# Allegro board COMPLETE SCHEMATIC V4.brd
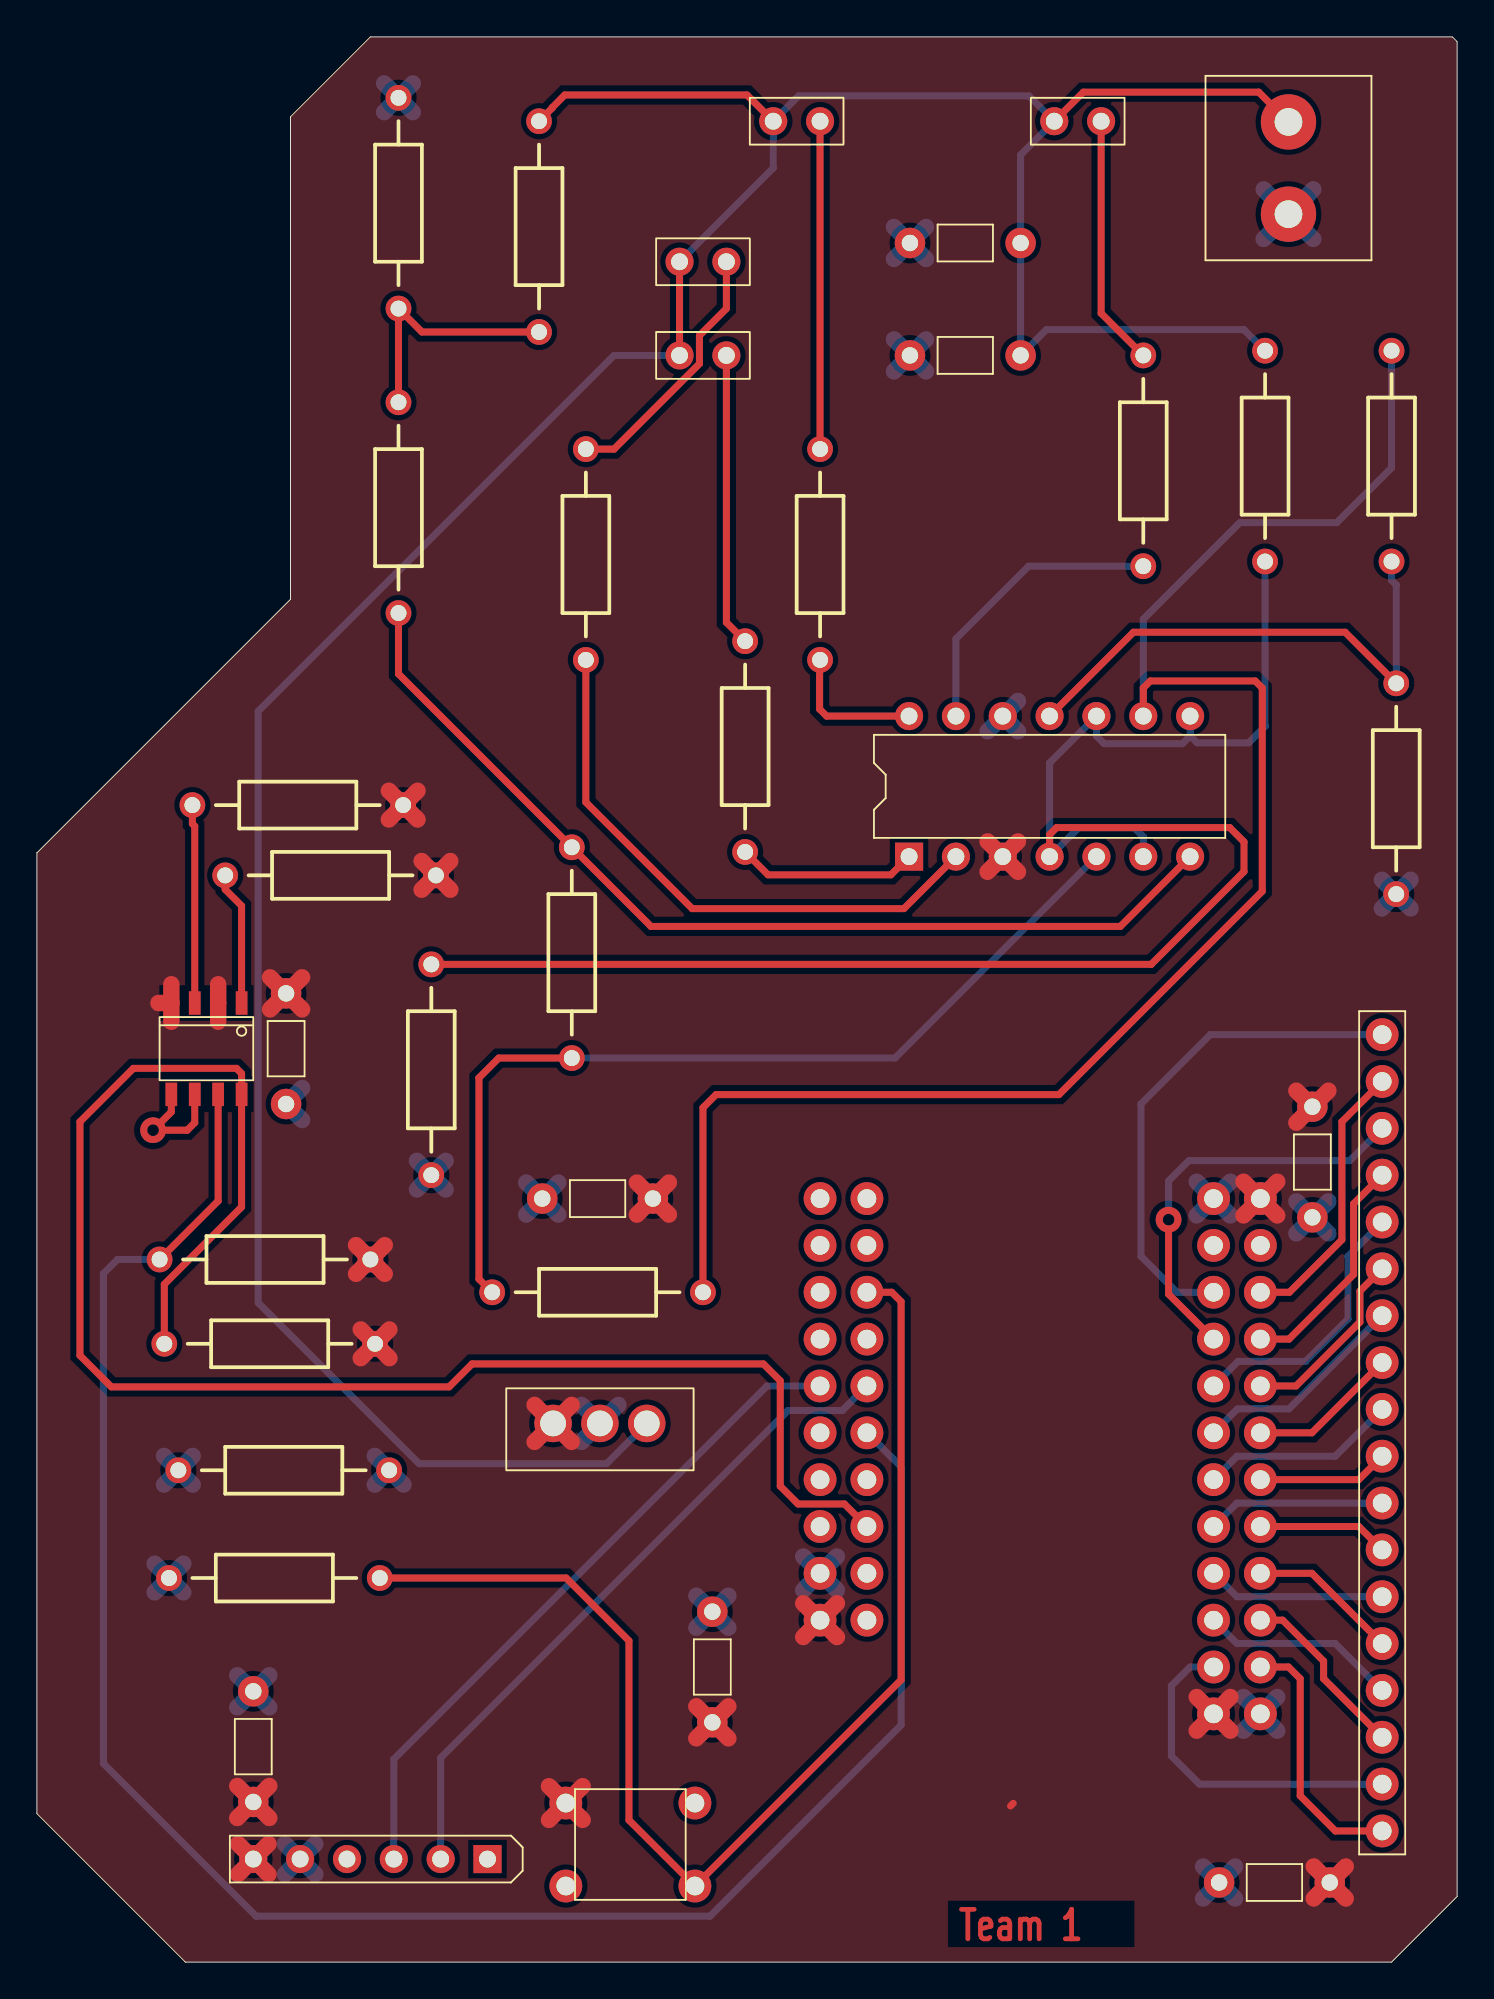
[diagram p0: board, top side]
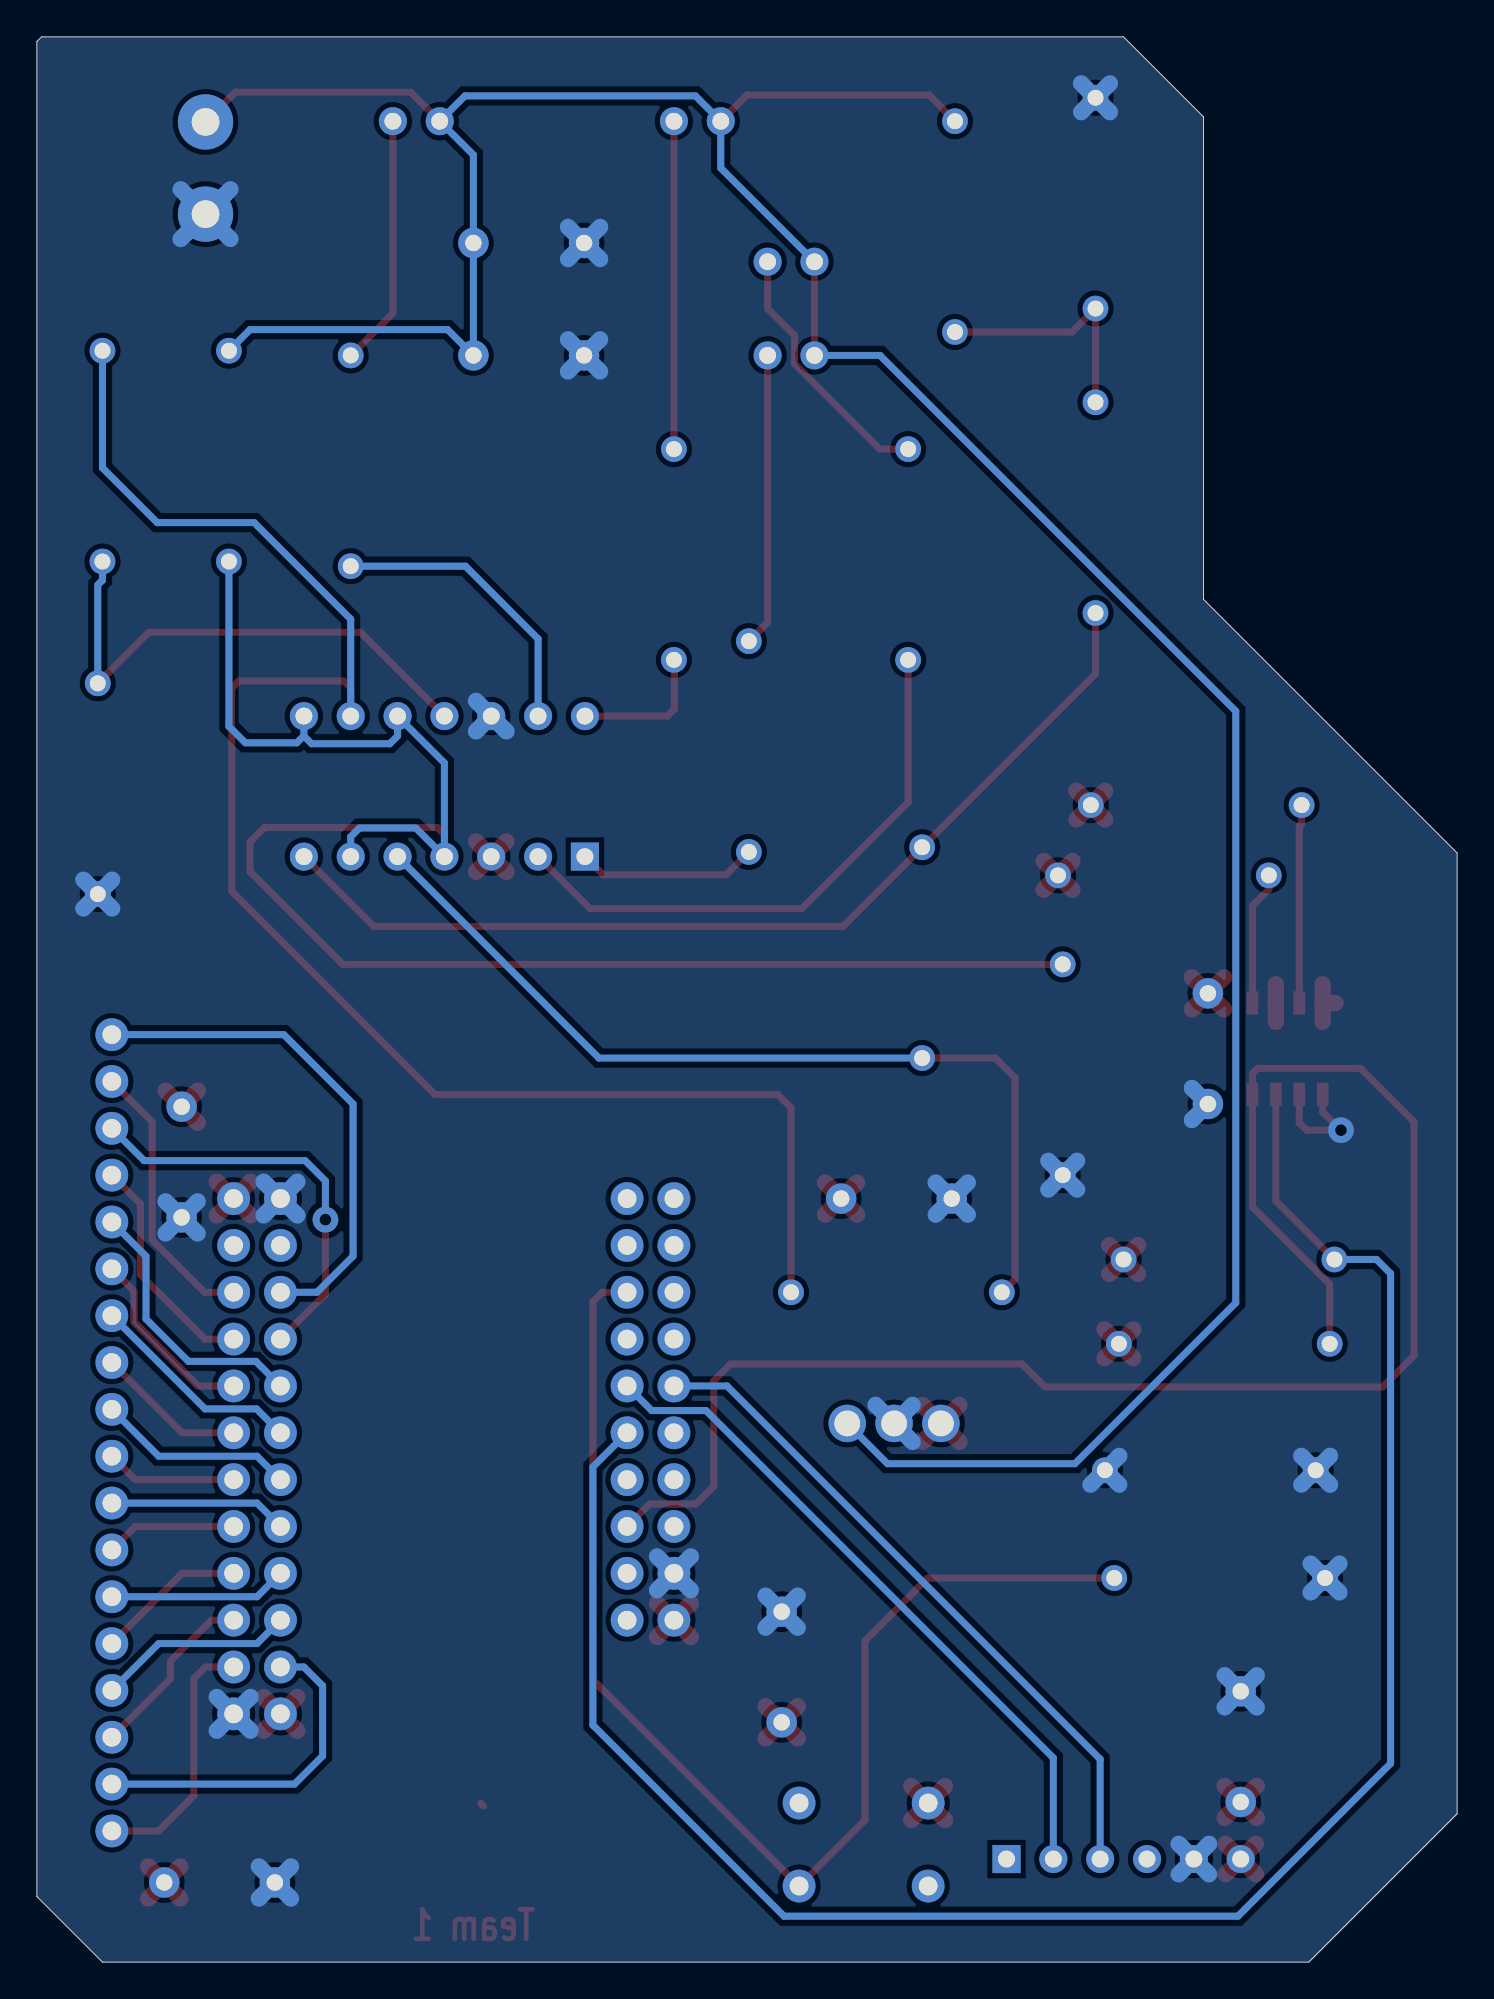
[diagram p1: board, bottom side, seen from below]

Outline 77.01 x 104.39 mm; copper layers: TOP, BOTTOM. Coordinates in mm from the lower left corner of the outline.
Outline path: 0,60.15 0,8.05 8.05,0 73.46,0 77.01,3.56 77.01,104.14 76.76,104.39 18.08,104.39 13.75,100.06 13.75,73.9 0,60.15

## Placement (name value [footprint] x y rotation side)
BT1  BATTERY  [2POS5MMCON]  67.87 97.28 0 top
C1  0.33uF 50V  [CAP1]  50.34 87.12 180 top
C2  0.1uF 50V  [CAP1]  30.4 41.4 180 top
C3  0.1uF 50V  [CAP1]  50.34 93.22 180 top
C4  0.1uF 50V  [CAP1]  36.63 16 90 top
C5  0.1 uF 50V  [CAP1]  69.16 43.38 270 top
C6  0.1uF 50V  [CAP1]  67.11 4.32 180 top
C7  0.1uF 50V  [CAP1]  11.73 11.68 270 top
C8  CAP NP  [CAP1]  13.51 49.53 270 top
D1  BLU  [JUMPER2]  34.85 87.12 0 top
D2  GRN  [JUMPER2]  34.85 92.2 0 top
D3  1N4733A  [AXRC07]  19.61 89.66 90 top
D4  YEL  [JUMPER2]  39.93 99.82 0 top
D5  RED  [JUMPER2]  55.17 99.82 0 top
D6  1N4001  [AXRC07]  7.67 26.67 0 top
J1  HEADER 6  [SIP6]  24.43 5.59 270 top
J2  HEADER 18  [HEADER_18]  72.95 28.7 0 top
R1  200 1/4W  [AXRC07]  27.23 99.82 270 top
R2  10k 1/4W  [AXRC07]  66.6 87.38 270 top
R3  500 1/4W  [AXRC07]  38.4 71.63 270 top
R4  2k 1/4W  [AXRC07]  19.61 84.58 270 top
R5  500 1/4W  [AXRC07]  29.77 82.04 270 top
R6  1k 1/4W  [AXRC07]  29.01 60.45 270 top
R7  470 1/4W  [AXRC07]  42.47 82.04 270 top
R8  1k 1/4W  [AXRC07]  24.69 36.32 0 top
R9  470 1/4W  [AXRC07]  59.99 87.12 270 top
R10  1k 1/4W  [AXRC07]  73.46 87.38 270 top
R11  12k 1/4W  [AXRC07]  73.71 69.34 270 top
R12  5k 1/4W  [AXRC07]  21.39 54.1 270 top
R13  10k 1/4W  [AXRC07]  18.59 20.83 180 top
R14  R  [AXRC07]  18.34 33.53 180 top
R15  R  [AXRC07]  18.08 38.1 180 top
R16  R  [AXRC07]  19.86 62.74 180 top
R17  R  [AXRC07]  21.64 58.93 180 top
SW1  SW PUSHBUTTON-SPST-2  [BUTTON]  32.18 6.38 0 top
U1  LM7805  [TO220AB]  33.07 29.21 0 top
U3  PSoC4BLE  [PSOC4BLE]  42.47 41.4 0 top
U4  LM339  [DIP14_3]  47.29 59.94 90 top
U5  ds3231  [SOIC8]  9.19 49.53 270 top

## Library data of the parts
BT1 = BATTERY
C1 C2 C4-C8 = CAP NP
C3 = C_0
D1 = LED_0: User Part Number: ***
D2 D4 D5 = LED_1: User Part Number: ***
D3 = DIODE ZENER_0
D6 = DIODE_0
J1 = HEADER 6_0: User Part Number: ***
J2 = HEADER 18
R1-R17 = R
SW1 = SW PUSHBUTTON-SPST-2
U1 = Linear regulator
U3 = PSoC4BLE_0
U4 = LM339_15: Tolerance: ***; User Part Number: ***
U5 = ds3231_0: Tolerance: ***; User Part Number: ***

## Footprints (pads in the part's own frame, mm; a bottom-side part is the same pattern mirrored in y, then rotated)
2POS5MMCON
  round 3 hole 1.5: 1(0,2.5) 2(0,-2.5)
AXRC07
  round 1.397 hole 0.864: 1(0,0) 2(11.43,0)
BUTTON
  round 1.778 hole 1.016: 1(-3.5,2.25) 2(-3.5,-2.25) 3(3.5,-2.25) 4(3.5,2.25)
CAP1
  round 1.651 hole 0.889: 1(-3,0) 2(3,0)
DIP14_3
  rect 1.524x1.524 hole 0.914: 1(0,0)
  round 1.524 hole 0.914: 2(0,-2.54) 3(0,-5.08) 4(0,-7.62) 5(0,-10.16) 6(0,-12.7) 7(0,-15.24) 8(7.62,-15.24) 9(7.62,-12.7) 10(7.62,-10.16) 11(7.62,-7.62) 12(7.62,-5.08) 13(7.62,-2.54) 14(7.62,0)
HEADER_18
  round 1.778 hole 1.016: 1(0,21.59) 2(0,19.05) 3(0,16.51) 4(0,13.97) 5(0,11.43) 6(0,8.89) 7(0,6.35) 8(0,3.81) 9(0,1.27) 10(0,-1.27) 11(0,-3.81) 12(0,-6.35) 13(0,-8.89) 14(0,-11.43) 15(0,-13.97) 16(0,-16.51) 17(0,-19.05) 18(0,-21.59)
JUMPER2
  round 1.524 hole 0.914: 1(0,0) 2(2.54,0)
PSOC4BLE
  round 1.778 hole 1.016: 1(2.54,-22.86) 2(0,-22.86) 3(2.54,-20.32) 4(0,-20.32) 5(2.54,-17.78) 6(0,-17.78) 7(2.54,-15.24) 8(0,-15.24) 9(2.54,-12.7) 10(0,-12.7) 11(2.54,-10.16) 12(0,-10.16) 13(2.54,-7.62) 14(0,-7.62) 15(2.54,-5.08) 16(0,-5.08) 17(2.54,-2.54) 18(0,-2.54) 19(2.54,0) 20(0,0) 21(21.336,0) 22(23.876,0) 23(21.336,-2.54) 24(23.876,-2.54) 25(21.336,-5.08) 26(23.876,-5.08) 27(21.336,-7.62) 28(23.876,-7.62) 29(21.336,-10.16) 30(23.876,-10.16) 31(21.336,-12.7) 32(23.876,-12.7) 33(21.336,-15.24) 34(23.876,-15.24) 35(21.336,-17.78) 36(23.876,-17.78) 37(21.336,-20.32) 38(23.876,-20.32) 39(21.336,-22.86) 40(23.876,-22.86) 41(21.336,-25.4) 42(23.876,-25.4) 43(21.336,-27.94) 44(23.876,-27.94)
SIP6
  rect 1.524x1.524 hole 0.914: 1(0,0)
  round 1.524 hole 0.914: 2(0,-2.54) 3(0,-5.08) 4(0,-7.62) 5(0,-10.16) 6(0,-12.7)
SOIC8
  rect 1.27x0.635 smd: 1(-2.477,1.905) 2(-2.477,0.635) 3(-2.477,-0.635) 4(-2.477,-1.905) 5(2.477,-1.905) 6(2.477,-0.635) 7(2.477,0.635) 8(2.477,1.905)
TO220AB
  round 2.032 hole 1.397: 1(0,0) 2(-2.54,0) 3(-5.08,0)

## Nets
+VBAT: BT1.1(+) C1.1 C3.1 D1.1 D2.1 D4.1 D5.1 R1.1 R2.1 U1.1(INPUT)
GND: BT1.2(-) C1.2 C2.2 C3.2 C4.2 C5.2 C6.2 C7.1 C8.2 D3.2(ANODE) D6.1 D6.2 J1.5(GND) R11.2 R12.2 R13.2 U1.2(GEOUND) U3.4(GND1) U3.21(GND2) U3.44(GND3) U4.12 U5.5(GND) U5.6(VBAT)
+5 V: C2.1 C4.1 C5.1 C6.1 C7.2 C8.1 J1.6(VCC) R14.1 R15.1 R16.1 R17.1 SW1.1 U1.3(OUTPUT) U3.2(VDDD) U3.22(VDDA) U3.43(VDDR) U4.3 U5.2(VCC) U5.4(R\S\T\)
RXD: J1.2(RXD) U3.11(P1.1)
SCL: R14.2 U3.5(P1.5) U5.8(SCL)
SDA: R15.2 U3.9(P1.4) U5.7(SDA)
TXD: J1.3(TXD) U3.12(P1.2)
N56194: R3.2 U4.1(OUT)
N56202: R5.2 U4.2(OUT)
N56210: R7.2 U4.14(OUT)
N56218: R9.2 U4.13(OUT)
N56230: D3.1(CATHODE) R1.2 R4.1
N56234: R4.2 R6.1 U4.7(+IN)
N56238: R6.2 R8.1 U4.5(+IN)
N56242: R8.2 R10.1 U4.9(+IN)
N56246: R2.2 R12.1 U4.4(-IN) U4.6(-IN) U4.8(-IN) U4.10(-IN)
N56362: R10.2 R11.1 U4.11(+IN)
N56366: D2.2 R5.1
N56370: D4.2 R7.1
N56374: D5.2 R9.1
N56918: R13.1 SW1.3 U3.15(P0.4)
N57246: J2.18 U3.42(P2.1)
N57250: J2.17 U3.41(P2.0)
N57254: J2.16 U3.40(P2.3)
N57258: J2.15 U3.39(P2.2)
N57262: J2.14 U3.38(P2.5)
N57266: J2.13 U3.37(P2.4)
N57270: J2.12 U3.36(P2.7)
N57274: J2.11 U3.35(P2.6)
N57278: J2.10 U3.34(P5.0)
N57282: J2.9 U3.33(P4.1)
N57286: J2.8 U3.32(P5.1)
N57290: J2.7 U3.31(P4.0)
N57294: J2.6 U3.30(P3.1)
N57298: J2.5 U3.29(P3.0)
N57318: J2.4 U3.28(P3.3)
N57322: J2.3 U3.27(P3.2)
N57332: J2.2 U3.26(P3.5)
N57336: J2.1 U3.25(P3.4)
N86841: R16.2 U5.3(I\N\T\/SQW)
N86845: R17.2 U5.1(32KHZ)
N561581: D1.2 R3.1

Pads without a net: J1 1 4; SW1 2 4; U3 1 3 6 7 8 10 13 14 16 17 18 19 20 23 24

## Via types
v1: diameter 1.397, hole 0.635, TOP to BOTTOM, 2 vias

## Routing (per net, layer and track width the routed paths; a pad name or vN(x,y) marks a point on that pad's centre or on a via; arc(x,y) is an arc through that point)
+VBAT: length 175.4
  TOP w0.381: BT1.1 66.25,101.4 56.74,101.4 D5.1 ; D4.1 38.51,101.24 28.63,101.24 27.95,100.57 27.95,100.54 R1.1 ; D1.1 D2.1
  BOTTOM w0.381: D2.1 39.93,97.28 D4.1 41.3,101.19 53.8,101.19 D5.1 53.34,98 C3.1 C1.1 54.74,88.52 65.46,88.52 R2.1 ; U1.1 30.89,27.03 20.73,27.03 12,35.75 12,67.83 31.29,87.12 D1.1
GND: length 104
  TOP w0.381: U5.6 8.56,45.52 8.15,45.11 v1(6.3,45.11) 7.29,46.1 U5.5
  BOTTOM w0.889: D3.2 20.39,100.31 ; D3.2 18.83,100.31 ; D3.2 20.39,101.87 ; D3.2 18.83,101.87 ; 41.56,20.17 U3.4 ; U3.4 41.56,22 ; U3.4 43.38,20.17 ; U3.4 43.38,22 ; 51.55,66.74 U4.12 ; U4.12 53.2,66.74 ; U4.12 53.2,68.39 ; R12.2 22.17,43.45 ; R12.2 20.61,43.45 ; R12.2 22.17,41.89 ; R12.2 20.61,41.89 ; 10.87,15.55 C7.1 ; C7.1 12.6,15.55 ; C7.1 10.87,13.82 ; C7.1 12.6,13.82 ; 72.93,58.69 R11.2 ; R11.2 74.49,57.13 ; R11.2 72.93,57.13 ; R11.2 74.49,58.69 ; BT1.2 69.21,96.13 ; BT1.2 66.52,96.13 ; BT1.2 69.21,93.44 ; BT1.2 66.52,93.44 ; 68.3,41.25 C5.2 ; C5.2 68.3,39.51 ; C5.2 70.03,39.51 ; C5.2 70.03,41.25 ; C2.2 28.27,40.53 ; C2.2 26.54,40.53 ; C2.2 28.27,42.27 ; C2.2 26.54,42.27 ; U3.21 64.72,42.32 ; U3.21 62.89,40.49 ; U3.21 64.72,40.49 ; U3.21 62.89,42.32 ; 46.47,86.25 C1.2 ; C1.2 46.47,87.99 ; C1.2 48.21,87.99 ; C1.2 48.21,86.25 ; D6.1 8.45,25.89 ; D6.1 6.89,27.45 ; D6.1 6.89,25.89 ; D6.1 8.45,27.45 ; 35.76,18.13 C4.2 ; C4.2 35.76,19.87 ; C4.2 37.5,18.13 ; C4.2 37.5,19.87 ; U3.44 67.26,14.38 ; U3.44 65.43,14.38 ; U3.44 67.26,12.55 ; U3.44 65.43,12.55 ; 18.32,27.45 D6.2 ; D6.2 19.88,25.89 ; D6.2 18.32,25.89 ; J1.5 15.1,4.76 ; J1.5 13.45,6.41 ; J1.5 15.1,6.41 ; J1.5 13.45,4.76 ; 63.24,3.45 C6.2 ; C6.2 64.98,3.45 ; C6.2 64.98,5.19 ; C6.2 63.24,5.19 ; 29.53,30.21 U1.2 ; U1.2 29.53,28.21 ; U1.2 31.53,30.21 ; R13.2 7.94,20.05 ; R13.2 7.94,21.61 ; R13.2 6.38,20.05 ; R13.2 6.38,21.61 ; 14.38,47.4 C8.2 14.38,45.66 ; C3.2 48.21,92.35 ; C3.2 48.21,94.09 ; C3.2 46.47,94.09 ; C3.2 46.47,92.35
+5 V: length 86.5
  TOP w0.381: 52.94,8.61 52.8,8.47
  TOP w0.889: 27.77,7.71 SW1.1 ; SW1.1 27.77,9.54 ; SW1.1 29.6,9.54 ; SW1.1 29.6,7.71 ; 69.24,5.19 C6.1 ; C6.1 70.98,3.45 ; C6.1 69.24,3.45 ; C6.1 70.98,5.19 ; C8.1 14.38,53.4 ; C8.1 12.64,51.66 ; C8.1 14.38,51.66 ; C8.1 12.64,53.4 ; R16.1 20.64,63.52 ; R16.1 19.08,63.52 ; R16.1 20.64,61.96 ; R16.1 19.08,61.96 ; R14.1 19.12,32.75 ; R14.1 19.12,34.31 ; R14.1 17.56,34.31 ; R14.1 17.56,32.75 ; 51.55,59.12 U4.3 ; U4.3 51.55,60.77 ; U4.3 53.2,60.77 ; U4.3 53.2,59.12 ; 65.43,42.32 U3.22 ; U3.22 67.26,42.32 ; U3.22 65.43,40.49 ; U3.22 67.26,40.49 ; C7.2 12.6,9.55 ; C7.2 12.6,7.82 ; C7.2 10.87,9.55 ; C7.2 10.87,7.82 ; C5.1 70.03,47.25 ; C5.1 68.3,47.25 ; C5.1 68.3,45.51 ; C4.1 37.5,12.13 ; C4.1 35.76,12.13 ; C4.1 35.76,13.87 ; C4.1 37.5,13.87 ; 32.54,40.53 C2.1 ; C2.1 34.27,42.27 ; C2.1 32.54,42.27 ; C2.1 34.27,40.53 ; 9.83,53.02 U5.2 9.83,50.99 ; 41.56,19.46 U3.2 ; U3.2 41.56,17.63 ; U3.2 43.38,19.46 ; U3.2 43.38,17.63 ; 6.59,52.01 U5.4 ; U5.4 7.29,50.99 ; U5.4 7.29,53.02 ; U1.3 28.99,28.21 ; U1.3 28.99,30.21 ; U1.3 26.99,30.21 ; U1.3 26.99,28.21 ; U3.43 64.72,14.38 ; U3.43 62.89,14.38 ; U3.43 64.72,12.55 ; U3.43 62.89,12.55 ; 17.31,37.32 R15.1 ; R15.1 18.86,38.88 ; R15.1 17.31,38.88 ; R15.1 18.86,37.32 ; 10.91,6.41 J1.6 ; J1.6 10.91,4.76 ; J1.6 12.56,4.76 ; J1.6 12.56,6.41 ; 20.86,58.15 R17.1 ; R17.1 22.42,58.15 ; R17.1 22.42,59.71 ; R17.1 20.86,59.71
RXD: length 37
  BOTTOM w0.381: J1.2 21.89,11.07 40.73,29.91 43.68,29.91 U3.11
SCL: length 90
  TOP w0.381: U3.5 43.79,24.84 41.28,24.84 40.31,25.81 40.31,31.52 39.4,32.44 23.6,32.44 22.35,31.19 4.04,31.19 2.34,32.89 2.34,45.57 5.23,48.46 10.82,48.46 11.1,48.18 U5.8 11.1,40.94 6.91,36.75 R14.2
SDA: length 107.8
  TOP w0.381: U5.7 9.83,41.27 R15.2
  BOTTOM w0.381: R15.2 4.37,38.1 3.61,37.34 3.61,10.77 11.89,2.49 36.5,2.49 46.86,12.85 46.86,26.85 U3.9
TXD: length 36.9
  BOTTOM w0.381: U3.12 39.59,31.24 19.35,11.01 J1.3
N56194: length 9.8
  TOP w0.381: U4.1 46.31,58.96 39.65,58.96 R3.2
N56202: length 31.3
  TOP w0.381: R5.2 29.77,62.89 35.53,57.12 47.02,57.12 U4.2
N56210: length 7.7
  TOP w0.381: U4.14 42.82,67.56 42.44,67.94 42.44,70.59 R7.2
N56218: length 16
  BOTTOM w0.381: R9.2 53.77,75.69 49.83,71.75 U4.13
N56230: length 13.2
  TOP w0.381: R1.2 20.88,88.39 D3.1 R4.1
N56234: length 53.5
  TOP w0.381: U4.7 58.75,56.16 33.3,56.16 R6.1 19.61,69.85 R4.2
N56238: length 50.4
  TOP w0.381: R8.1 23.97,37.04 23.97,47.95 25.04,49.02 R6.2
  BOTTOM w0.381: U4.5 46.53,49.02 R6.2
N56242: length 93
  TOP w0.381: R8.2 36.12,46.33 36.83,47.04 55.42,47.04 66.45,58.06 66.45,69.09 66.07,69.47 60.38,69.47 59.99,69.09 U4.9
  BOTTOM w0.381: U4.9 59.99,72.82 65.23,78.05 70.48,78.05 73.46,81.03 R10.1
N56246: length 96.8
  TOP w0.381: R12.1 60.43,54.1 65.46,59.13 65.46,60.74 64.68,61.52 55.3,61.52 54.91,61.14 U4.4
  BOTTOM w0.381: 62.53,66.5 62.92,66.12 65.71,66.12 66.6,67.01 R2.2 ; 62.53,66.5 U4.8 ; 62.53,66.5 62.53,66.48 62.12,66.07 57.87,66.07 57.45,66.48 U4.10 54.91,65.02 U4.4 56.46,61.49 59.52,61.49 59.99,61.02 U4.6
N56362: length 28.5
  TOP w0.381: U4.11 59.46,72.11 70.94,72.11 R11.1
  BOTTOM w0.381: R10.2 73.46,74.93 73.71,74.68 R11.1
N56366: length 14.2
  TOP w0.381: R5.1 31.3,82.04 35.93,86.67 35.93,88.2 37.39,89.66 D2.2
N56370: length 17.8
  TOP w0.381: R7.1 D4.2
N56374: length 13.6
  TOP w0.381: R9.1 57.71,89.41 D5.2
N56918: length 68.1
  TOP w0.381: U3.15 46.36,36.32 46.86,35.81 46.86,15.31 SW1.3 32.11,7.7 32.11,17.42 28.7,20.83 R13.1
N57246: length 14
  TOP w0.381: U3.42 67.87,16 68.5,15.37 68.5,9.02 70.41,7.11 J2.18
N57250: length 18.6
  BOTTOM w0.381: U3.41 62.53,16 61.52,14.99 61.52,11.18 63.04,9.65 J2.17
N57254: length 9.8
  TOP w0.381: J2.16 69.77,15.37 69.77,16.32 67.55,18.54 U3.40
N57258: length 10.7
  BOTTOM w0.381: U3.39 65.07,17.27 70.41,17.27 J2.15
N57262: length 8.2
  TOP w0.381: J2.14 69.14,21.08 U3.38
N57266: length 9.7
  BOTTOM w0.381: J2.13 65.07,19.81 U3.37
N57270: length 7.1
  TOP w0.381: U3.36 71.68,23.62 J2.12
N57274: length 9.7
  BOTTOM w0.381: U3.35 65.07,24.89 J2.11
N57278: length 7.1
  TOP w0.381: U3.34 71.68,26.16 J2.10
N57282: length 10.7
  BOTTOM w0.381: U3.33 65.07,27.43 70.41,27.43 J2.9
N57286: length 8.2
  TOP w0.381: J2.8 69.14,28.7 U3.32
N57290: length 11.8
  BOTTOM w0.381: U3.31 65.1,30 67.89,30 J2.7
N57294: length 10.2
  TOP w0.381: J2.6 71.74,36.39 71.74,34.71 68.28,31.24 U3.30
N57298: length 14.8
  BOTTOM w0.381: U3.29 65.14,32.58 68.8,32.58 71.09,34.87 71.09,38.28 J2.5
N57318: length 12.5
  TOP w0.381: J2.4 71.4,41.12 71.4,37.29 67.89,33.78 U3.28
N57322: length 22.4
  TOP w0.381: U3.27 61.37,36.22 v1(61.37,40.26)
  BOTTOM w0.381: v1(61.37,40.26) 61.37,42.36 62.47,43.46 71.2,43.46 J2.3
N57332: length 15.1
  TOP w0.381: J2.2 70.76,45.57 70.76,39.17 67.92,36.32 U3.26
N57336: length 27.6
  BOTTOM w0.381: U3.25 61.82,36.32 59.87,38.28 59.87,46.53 63.63,50.29 J2.1
N86841: length 10.8
  TOP w0.381: U5.3 8.56,61.59 8.43,61.72 R16.2
N86845: length 7.3
  TOP w0.381: R17.2 10.21,58.17 11.1,57.28 U5.1
N561581: length 15.9
  TOP w0.381: D1.2 37.39,72.64 R3.1

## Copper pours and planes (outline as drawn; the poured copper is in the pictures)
GND on BOTTOM: 77.01,3.56 77.01,104.14 76.76,104.39 18.08,104.39 13.77,100.08 13.77,73.91 0,60.15 0,7.95 7.95,0 73.46,0
+5 V on TOP: 77.01,3.56 77.01,104.14 76.76,104.39 18.08,104.39 13.75,100.06 13.75,73.9 0,60.15 0,8.05 8.05,0 73.46,0

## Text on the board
TOP: Team 1
